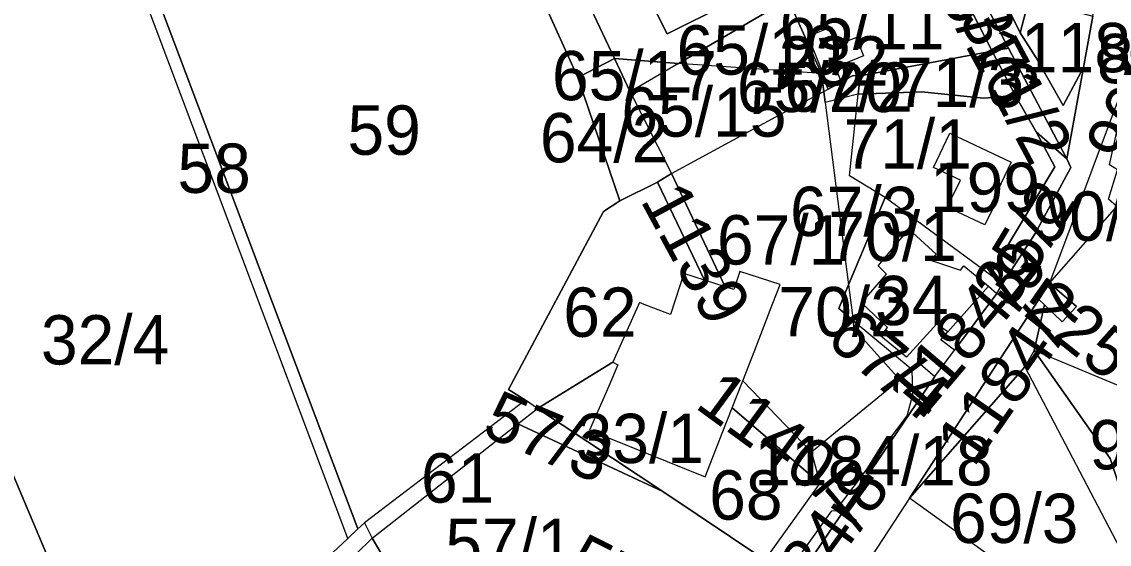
# Model space of a CAD drawing. Extents: x -623250 to -619626, y -1079612 to -1075424.
# Drawn here: x -621589.3 to -621368.8, y -1077196.3 to -1077090.4 of the extents above; entities that cross this region are included whole.
import ezdxf

# ---------------------------------------------------------------- set-up
doc = ezdxf.new("R2010")
doc.units = 0
doc.layers.add('Parcela nároku', color=7, linetype='Continuous')
doc.layers.add('Parcelní číslo', color=7, linetype='Continuous')

msp = doc.modelspace()

# ---------------------------------------------------------------- linework, layer by layer
at = {"layer": 'Parcela nároku'}
for points in [[(-621276.33, -1076904.65), (-621286.38, -1076922.74), (-621293.22, -1076935.57), (-621298.92, -1076946.24), (-621309.78, -1076966.57), (-621316.49, -1076979.64), (-621324.93, -1076996.07), (-621326.25, -1076998.64), (-621328.09, -1077002.19), (-621334.09, -1077013.79), (-621344.48, -1077034.16), (-621351.33, -1077048.78), (-621355.43, -1077057.52), (-621357.91, -1077065.42), (-621359.83, -1077071.59), (-621363.46, -1077083.65), (-621362.11, -1077084.13), (-621362.86, -1077089.41), (-621364.18, -1077098.66), (-621380.94, -1077143.37), (-621383.09, -1077146.69), (-621409.34, -1077186.93), (-621429.78, -1077218.32)], [(-621432.3, -1077203.73), (-621404.2, -1077162.3), (-621400.21, -1077156.98), (-621391.61, -1077145.5), (-621390.49, -1077143.5), (-621383.83, -1077133.32), (-621376.62, -1077119.92), (-621377.43, -1077118.16), (-621374.04, -1077099.65), (-621372.14, -1077089.23), (-621370.85, -1077081.53), (-621365.54, -1077073.2), (-621364.82, -1077065.54), (-621362.74, -1077065.56), (-621350.29, -1077025.63), (-621323.26, -1076972.15), (-621322.86, -1076971.35), (-621322.12, -1076969.47), (-621319.23, -1076962.06), (-621309.08, -1076943.03), (-621308.57, -1076943.53), (-621302.09, -1076930.63), (-621298.1, -1076925.1), (-621290.94, -1076911.65)], [(-621399.54, -1077067.08), (-621386.89, -1077092.62), (-621383.67, -1077097.7), (-621378.21, -1077107.34), (-621374.04, -1077099.65), (-621377.43, -1077118.16), (-621389.23, -1077095.72), (-621393.93, -1077086.79)], [(-621474.53, -1077086.43), (-621469.13, -1077097.83), (-621476.57, -1077101.71), (-621483.91, -1077085.32)], [(-621361.11, -1077201.81), (-621368.64, -1077178.95), (-621384.05, -1077157.04), (-621385.94, -1077160.33), (-621365.2, -1077199.94)]]:
    msp.add_lwpolyline(points, dxfattribs=at)
for points in [[(-621552.14, -1077054.14), (-621509.39, -1077032.53), (-621483.91, -1077085.32), (-621476.57, -1077101.71), (-621468.03, -1077126.7), (-621471.34, -1077128.84), (-621490.6, -1077164.95), (-621487.16, -1077167.11), (-621519.83, -1077191.99), (-621521.13, -1077193.21), (-621569.59, -1077064.81)], [(-621389.91, -1077057.9), (-621374.82, -1077088.56), (-621380.86, -1077086.97), (-621385.12, -1077085.85), (-621386.89, -1077092.62), (-621399.54, -1077067.08)], [(-621571.7, -1077066.1), (-621569.59, -1077064.81), (-621521.13, -1077193.21), (-621523.17, -1077195.12)], [(-621523.17, -1077195.12), (-621571.7, -1077066.1), (-621579.59, -1077070.93), (-621623.27, -1077105.92), (-621571.51, -1077228.57), (-621549.32, -1077220.52), (-621537.72, -1077208.73)], [(-621468.66, -1077072.65), (-621456.74, -1077066.63), (-621452.46, -1077075.11), (-621446.52, -1077086.85), (-621458.44, -1077092.81), (-621464.33, -1077081.2)], [(-621423.19, -1077102.63), (-621425.84, -1077104.04), (-621427.19, -1077100.87), (-621433.93, -1077085.81), (-621430.77, -1077083.96), (-621405.61, -1077069.31), (-621395.26, -1077087.55), (-621396.48, -1077088.72), (-621392.58, -1077096.32), (-621419.31, -1077101.34), (-621420.72, -1077101.24), (-621421.54, -1077101.66)], [(-621442.52, -1077070.01), (-621435.46, -1077082.99), (-621433.93, -1077085.81), (-621456.15, -1077098.84), (-621469.13, -1077097.83), (-621474.53, -1077086.43), (-621464.33, -1077081.2), (-621458.44, -1077092.81), (-621446.52, -1077086.85), (-621452.46, -1077075.11)], [(-621433.93, -1077085.81), (-621427.19, -1077100.87), (-621456.15, -1077098.84)], [(-621393.93, -1077086.79), (-621389.23, -1077095.72), (-621392.58, -1077096.32), (-621396.48, -1077088.72), (-621395.26, -1077087.55)], [(-621374.82, -1077088.56), (-621373.89, -1077088.8), (-621372.14, -1077089.23), (-621374.04, -1077099.65), (-621378.21, -1077107.34), (-621383.67, -1077097.7), (-621386.89, -1077092.62), (-621385.12, -1077085.85), (-621380.86, -1077086.97)], [(-621423.19, -1077102.63), (-621425.69, -1077103.63), (-621426.93, -1077100.72), (-621429.89, -1077093.33), (-621425.11, -1077091.4), (-621423.69, -1077094.94), (-621420.17, -1077093.54), (-621418.65, -1077097.3), (-621423.25, -1077099.19), (-621424.35, -1077099.62)], [(-621425.11, -1077091.4), (-621423.69, -1077094.94), (-621420.17, -1077093.54), (-621418.65, -1077097.3), (-621423.25, -1077099.19), (-621424.35, -1077099.62), (-621423.19, -1077102.63), (-621425.69, -1077103.63), (-621426.93, -1077100.72), (-621429.89, -1077093.33)], [(-621389.23, -1077095.72), (-621377.43, -1077118.16), (-621383.67, -1077112.72), (-621387.84, -1077105.38), (-621392.58, -1077096.32)], [(-621465.94, -1077104.58), (-621457.57, -1077121.14), (-621460.38, -1077122.9), (-621468.03, -1077126.7), (-621476.57, -1077101.71), (-621469.13, -1077097.83)], [(-621469.13, -1077097.83), (-621456.15, -1077098.84), (-621465.94, -1077104.58)], [(-621392.58, -1077096.32), (-621387.84, -1077105.38), (-621394.32, -1077105.89), (-621406.89, -1077104.57), (-621419.71, -1077105.04), (-621419.31, -1077101.34)], [(-621426.72, -1077104.5), (-621427.19, -1077100.87), (-621456.15, -1077098.84), (-621465.94, -1077104.58), (-621457.57, -1077121.14), (-621435.67, -1077109.24)], [(-621367.14, -1077120.41), (-621368.81, -1077119.36), (-621364.18, -1077098.66), (-621380.94, -1077143.37), (-621367.29, -1077127.83), (-621369, -1077126.37)], [(-621425.84, -1077104.04), (-621427.19, -1077100.87), (-621426.72, -1077104.5)], [(-621423.19, -1077102.63), (-621421.54, -1077101.66), (-621420.72, -1077101.24), (-621419.31, -1077101.34), (-621419.71, -1077105.04), (-621419.82, -1077105.04), (-621426.43, -1077106.74), (-621426.72, -1077104.5), (-621425.84, -1077104.04)], [(-621443.1, -1077163.19), (-621440.66, -1077156.97), (-621437.03, -1077147.43), (-621435.56, -1077143.67), (-621443.73, -1077141.01), (-621444.92, -1077144.68), (-621446.68, -1077144.11), (-621457.57, -1077121.14), (-621435.67, -1077109.24), (-621426.72, -1077104.5), (-621426.43, -1077106.74), (-621421.67, -1077143.72), (-621423.67, -1077148.49), (-621420.74, -1077150.93), (-621420.52, -1077152.63), (-621411.32, -1077162.97), (-621429.17, -1077177.61)], [(-621421.51, -1077121.62), (-621419.71, -1077105.04), (-621406.89, -1077104.57), (-621394.32, -1077105.89), (-621387.84, -1077105.38), (-621383.67, -1077112.72), (-621379.84, -1077119.76), (-621392.98, -1077141.67), (-621414.24, -1077126.01)], [(-621570.38, -1077230.98), (-621571.51, -1077228.57), (-621623.27, -1077105.92), (-621674.17, -1077133.23), (-621673.7, -1077140.26), (-621670.74, -1077164.6), (-621661.04, -1077207.94), (-621624.64, -1077201.52), (-621606.64, -1077245.37), (-621587.33, -1077241.87)], [(-621419.82, -1077105.04), (-621426.43, -1077106.74), (-621421.67, -1077143.72), (-621414.24, -1077126.01), (-621421.51, -1077121.62), (-621419.71, -1077105.04)], [(-621399.02, -1077122.51), (-621404.47, -1077119.93), (-621401.17, -1077112.93), (-621388.69, -1077118.81), (-621392.88, -1077127.64), (-621392.32, -1077127.94), (-621394.07, -1077131.56), (-621401.66, -1077127.94)], [(-621392.88, -1077127.64), (-621392.32, -1077127.94), (-621394.07, -1077131.56), (-621401.66, -1077127.94), (-621399.02, -1077122.51), (-621404.47, -1077119.93), (-621401.17, -1077112.93), (-621388.69, -1077118.81)], [(-621377.43, -1077118.16), (-621376.62, -1077119.92), (-621383.83, -1077133.32), (-621390.49, -1077143.5), (-621392.98, -1077141.67), (-621379.84, -1077119.76), (-621383.67, -1077112.72)], [(-621460.38, -1077122.9), (-621457.57, -1077121.14), (-621446.68, -1077144.11), (-621450.85, -1077142.75)], [(-621350.79, -1077130.97), (-621334, -1077138.41), (-621335.24, -1077144.05), (-621330.77, -1077177.42), (-621342.75, -1077185.94), (-621344.27, -1077183.78), (-621362.96, -1077165.79), (-621384.05, -1077157.04), (-621381.95, -1077147.79), (-621378.41, -1077151.2), (-621375.46, -1077148.11), (-621380.94, -1077143.37), (-621367.29, -1077127.83), (-621369, -1077126.37), (-621367.14, -1077120.41), (-621356.21, -1077127.29)], [(-621490.6, -1077164.95), (-621471.34, -1077128.84), (-621468.03, -1077126.7), (-621460.38, -1077122.9), (-621450.85, -1077142.75), (-621455.06, -1077141.38), (-621457.75, -1077149.7), (-621458.31, -1077149.49), (-621463.08, -1077147.72), (-621464.09, -1077147.28), (-621469.47, -1077159.41), (-621484.71, -1077168.81), (-621487.16, -1077167.11)], [(-621413.76, -1077152.35), (-621419.04, -1077147.38), (-621414.01, -1077141.55), (-621415.68, -1077139.87), (-621409.48, -1077132.42), (-621403.89, -1077137.51), (-621405.07, -1077138.69), (-621398.97, -1077140.72), (-621398.31, -1077139.87), (-621393.34, -1077143.99), (-621391.61, -1077145.5), (-621390.49, -1077143.5), (-621392.98, -1077141.67), (-621414.24, -1077126.01), (-621421.67, -1077143.72), (-621420.74, -1077150.93), (-621408.77, -1077160.88), (-621407.08, -1077159.8), (-621404.2, -1077162.3), (-621400.21, -1077156.98), (-621402.96, -1077154.83), (-621401.53, -1077153.22), (-621403.83, -1077151.67), (-621409.91, -1077158.37), (-621415.12, -1077154.09)], [(-621419.04, -1077147.38), (-621414.01, -1077141.55), (-621415.68, -1077139.87), (-621409.48, -1077132.42), (-621403.89, -1077137.51), (-621405.07, -1077138.69), (-621398.97, -1077140.72), (-621398.31, -1077139.87), (-621393.34, -1077143.99), (-621401.53, -1077153.22), (-621403.83, -1077151.67), (-621409.91, -1077158.37), (-621415.12, -1077154.09), (-621413.76, -1077152.35)], [(-621468.42, -1077159.96), (-621470.27, -1077164.23), (-621474.17, -1077173.17), (-621450.75, -1077182.63), (-621447.14, -1077173.47), (-621445.25, -1077168.67), (-621443.1, -1077163.19), (-621440.66, -1077156.97), (-621437.03, -1077147.43), (-621435.56, -1077143.67), (-621443.73, -1077141.01), (-621444.92, -1077144.68), (-621446.68, -1077144.11), (-621450.85, -1077142.75), (-621455.06, -1077141.38), (-621457.75, -1077149.7), (-621458.31, -1077149.49), (-621463.08, -1077147.72), (-621464.09, -1077147.28), (-621469.47, -1077159.41)], [(-621423.67, -1077148.49), (-621421.67, -1077143.72), (-621420.74, -1077150.93)], [(-621402.96, -1077154.83), (-621401.53, -1077153.22), (-621393.34, -1077143.99), (-621391.61, -1077145.5), (-621400.21, -1077156.98)], [(-621380.94, -1077143.37), (-621375.46, -1077148.11), (-621378.41, -1077151.2), (-621381.95, -1077147.79), (-621383.09, -1077146.69)], [(-621409.34, -1077186.93), (-621383.09, -1077146.69), (-621381.95, -1077147.79), (-621384.05, -1077157.04), (-621385.94, -1077160.33)], [(-621420.74, -1077150.93), (-621408.77, -1077160.88), (-621411.32, -1077162.97), (-621420.52, -1077152.63)], [(-621344.27, -1077183.78), (-621362.96, -1077165.79), (-621384.05, -1077157.04), (-621368.64, -1077178.95), (-621361.11, -1077201.81), (-621355.51, -1077199.95), (-621338.15, -1077192.45), (-621342.75, -1077185.94)], [(-621450.75, -1077182.63), (-621447.14, -1077173.47), (-621445.25, -1077168.67), (-621427.49, -1077183.9), (-621438.62, -1077199.49), (-621459.3, -1077185.63), (-621484.71, -1077168.81), (-621469.47, -1077159.41), (-621468.42, -1077159.96), (-621470.27, -1077164.23), (-621474.17, -1077173.17)], [(-621407.08, -1077159.8), (-621404.2, -1077162.3), (-621432.3, -1077203.73), (-621438.62, -1077199.49), (-621433.03, -1077200.65), (-621425.1, -1077189.5), (-621424.25, -1077189.49), (-621409.78, -1077170.25), (-621408.67, -1077165.96), (-621408.77, -1077160.88)], [(-621411.32, -1077162.97), (-621429.17, -1077177.61), (-621427.49, -1077183.9), (-621438.62, -1077199.49), (-621433.03, -1077200.65), (-621425.1, -1077189.5), (-621424.25, -1077189.49), (-621409.78, -1077170.25), (-621408.67, -1077165.96), (-621408.77, -1077160.88)], [(-621409.34, -1077186.93), (-621385.94, -1077160.33), (-621365.2, -1077199.94), (-621363.51, -1077210.97), (-621363.55, -1077212.6), (-621364.55, -1077219.18)], [(-621445.25, -1077168.67), (-621443.1, -1077163.19), (-621429.17, -1077177.61), (-621427.49, -1077183.9)], [(-621484.71, -1077168.81), (-621487.16, -1077167.11), (-621519.83, -1077191.99), (-621518.22, -1077195.04), (-621488.73, -1077171.92)], [(-621484.71, -1077168.81), (-621459.3, -1077185.63), (-621488.73, -1077171.92)], [(-621438.62, -1077199.49), (-621432.3, -1077203.73), (-621435.93, -1077208.63), (-621439.49, -1077207.28), (-621448.67, -1077201.99), (-621452.6, -1077208.52), (-621457.99, -1077205.53), (-621464.86, -1077201.73), (-621470.95, -1077198.36), (-621474.76, -1077204.68), (-621473.5, -1077205.38), (-621479.38, -1077216.29), (-621481.63, -1077220.46), (-621501.67, -1077213.97), (-621512.56, -1077204.65), (-621518.22, -1077195.04), (-621488.73, -1077171.92), (-621459.3, -1077185.63)], [(-621414.18, -1077278.35), (-621398.59, -1077263.79), (-621387.96, -1077259.7), (-621377.6, -1077252.01), (-621366.43, -1077227.54), (-621364.55, -1077219.18), (-621409.34, -1077186.93), (-621429.78, -1077218.32), (-621424.96, -1077221.94), (-621423.29, -1077233.96), (-621423.71, -1077270.11)], [(-621549.32, -1077220.52), (-621537.72, -1077208.73), (-621523.17, -1077195.12), (-621521.13, -1077193.21), (-621519.83, -1077191.99), (-621518.22, -1077195.04), (-621534.82, -1077211.31), (-621547.78, -1077223.78), (-621570.38, -1077230.98), (-621571.51, -1077228.57)], [(-621481.63, -1077220.46), (-621453.31, -1077229.64), (-621449.99, -1077231.49), (-621462.01, -1077253.72), (-621471.25, -1077272.91), (-621483.22, -1077260.93), (-621493.97, -1077256.98), (-621534.82, -1077211.31), (-621518.22, -1077195.04), (-621512.56, -1077204.65), (-621501.67, -1077213.97)]]:
    msp.add_lwpolyline(points, close=True, dxfattribs=at)

# ---------------------------------------------------------------- texts
at = {"layer": 'Parcelní číslo'}
for s, rotation, p in [('65/13', 299.237, (-621412.25, -1077067.1)), ('65/16', 298.2288, (-621407, -1077078.61)), ('71/2', 298.1261, (-621396.91, -1077097.17)), ('90/2', 63.0724, (-621365.2, -1077119.9)), ('1139', 298.3243, (-621463.99, -1077126.57)), ('35/2', 58.748, (-621388.55, -1077148.95)), ('1184/9', 49.7682, (-621407.06, -1077171.37)), ('1225', 321.5137, (-621392.37, -1077145.01)), ('1184/7', 55.1455, (-621396.32, -1077180.93)), ('67/4', 320.255, (-621426.64, -1077155.24)), ('1140/1', 323.7667, (-621453.08, -1077168.47)), ('57/3', 337.2072, (-621496.35, -1077174.05)), ('1184/8', 54.0048, (-621436.96, -1077217.95)), ('57/2', 333.1751, (-621479.59, -1077202.71))]:
    msp.add_text(s, height=10, rotation=rotation, dxfattribs=at).set_placement(p)
for s, p in [('65/11', (-621435.67, -1077095.95)), ('65/10', (-621456.55, -1077101.1)), ('118', (-621386.74, -1077100.61)), ('232', (-621435.88, -1077103.31)), ('87/2', (-621371.32, -1077102.83)), ('65/17', (-621481.8, -1077106.29)), ('67/2', (-621434.65, -1077108.62)), ('71/3', (-621412.09, -1077107.67)), ('65/20', (-621444.32, -1077108.68)), ('65/15', (-621467.73, -1077113.67)), ('59', (-621523.26, -1077117.34)), ('64/2', (-621484.25, -1077118.89)), ('71/1', (-621422.7, -1077120.15)), ('58', (-621557.72, -1077125.07)), ('199', (-621405.17, -1077128.95)), ('67/3', (-621433.55, -1077133.82)), ('90/1', (-621384.38, -1077134.78)), ('70/1', (-621425.77, -1077138.9)), ('67/1', (-621448.36, -1077139.59)), ('34', (-621416.3, -1077151.88)), ('62', (-621479.51, -1077154.25)), ('70/2', (-621435.9, -1077154.15)), ('32/4', (-621585.39, -1077159.86)), ('33/1', (-621477.01, -1077179.84)), ('93', (-621372.85, -1077181.12)), ('1184/18', (-621440.8, -1077184.38)), ('61', (-621508.36, -1077187.86)), ('68', (-621449.94, -1077191.31)), ('69/3', (-621401.11, -1077196.04)), ('57/1', (-621503.42, -1077201.11))]:
    msp.add_text(s, height=10, dxfattribs=at).set_placement(p)

doc.saveas('drawing.dxf')
